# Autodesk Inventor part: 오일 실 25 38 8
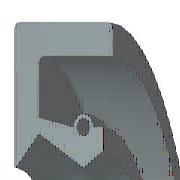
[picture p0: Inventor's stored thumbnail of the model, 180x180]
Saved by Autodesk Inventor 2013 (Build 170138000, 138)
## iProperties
Created: 2012-02
Part Number: 오일 실 25 38 8
Material: 고무
Description: 오일-실
Document SubType Name: Modeling
Standard: KS B 2804
Designer: mduedu
Standards Organization: KS
Language: ko-KR
Size Designation: D - 25 38 8
Categories: <MemberInstance><Categories><Category DisplayName="샤프트 부품" InternalName="7f7aeb1f-a693-4053-b835-cee3144e0d98" Mnemonic="SHFT"><Category DisplayName="실링" Intern
Density: 0.93 g/cm^3
Mass: 2.72583 g
Surface Area: 38.9868 cm^2
Volume: 2.931 cm^3
IsCustomPart: 1
Author: mduedu
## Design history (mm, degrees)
revolve "본체" stored, may be unused: angle "d17" = 90 deg
revolve "스프링1" stored, may be unused: angle "d18" = 90 deg
body "Solid1"
sketch "스케치1"
  geometry: L1 (0, 19)-(8, 19); L2 (8, 17.25)-(1.75, 17.25); L3 (1.75, 14.25)-(4.9, 12.5); L4 (4.9, 12.5)-(0, 12.5); L5 (0, 0)-(9.586, 0) reference; L6 (4.9, 12.5)-(6.3, 13.375); L7 (0, 18)-(0, -3) reference; L8 (-1.941, 0)-(11.507, 0) reference; L9 (4.2, 14.6)-(1.75, 15.21); L10 (1.75, 15.21)-(1.75, 17.25); L11 (0, 19)-(0, 12.588); L12 (4.9, 12.5)-(0, 12.5); L13 (1.75, 14.25)-(0.152, 12.528); L14 (8, 19)-(8, 17.25); L15 (5.6, 14.6)-(6.3, 14.6); L16 (6.3, 14.6)-(6.3, 13.375); C1 r 0.455 at (4.9, 14.6); A1 r 0.7 centre (4.9, 14.6) between (5.6, 14.6) and (4.2, 14.6); A2 r 0.088 centre (0.087, 12.588) between (0, 12.588) and (0.152, 12.528); 1 further point
  constraints: 28 end point, 5 horizontal alignment, 5 point on line, 4 point on circle, 4 vertical alignment, 3 centre point, 3 tangent, 2 collinear, 2 horizontal, 2 perpendicular, 1 coincident, 1 parallel
  dimensions: "d0" = 38 diameter of L1 L5 (= SD2); "d1" = 1.75 distance of L1.end L2.start (= SD); "d2" = 0.91 diameter of C1 (= SPDI); "d3" = 1.4 diameter of A1 (= SPDA); "d4" = 25 diameter of L3.end L5 (= NND); "d5" = 28.5 diameter of L3.start L5 (= TKDM); "d7" = 30.42 diameter of L9.end L5 (= TKDM + 0.24 x SWDT); "d8" = 1.75 distance between parallel lines of L11 L10 (= SD); "d9" = 4.9 distance from line of L11 C1.centre (= SPDST); "d10" = 29.2 diameter of C1.centre L5 (= HLDM); "d11" = 0.0875 radius of A2 (= 0.25 x LAB); "d12" = 6.3 distance between parallel lines of L11 L16 (= SDI); "d13" = 26.75 diameter of L6.end L5 (= ABDM); "d14" = 8 distance from line of L11 L1.end (= SWDT)
fillet "모깎기1" dims "d6" = 0.3 (= RR)
other parameters: "SD2" = 38 [user parameter; used in 1 equation term], "SWDT" = 8 [user parameter; used in 2 equation terms], "RR" = 0.3 [user parameter; used in 1 equation term], "SD" = 1.75 [user parameter; used in 2 equation terms], "NND" = 25 [user parameter; used in 1 equation term], "SPDA" = 1.4 [user parameter; used in 1 equation term], "SPDI" = 0.91 [user parameter; used in 1 equation term], "TKDM" = 28.5 [user parameter; used in 2 equation terms], "HLDM" = 29.2 [user parameter; used in 1 equation term], "ABDM" = 26.75 [user parameter; used in 1 equation term], "SDI" = 6.3 [user parameter; used in 1 equation term], "SPDST" = 4.9 [user parameter; used in 1 equation term], "LAB" = 0.35 [user parameter; used in 1 equation term], "d15" = 0, "d16" = 0, "d19" = 0
